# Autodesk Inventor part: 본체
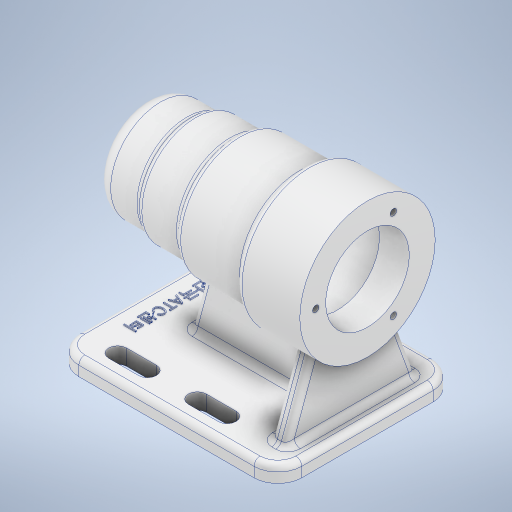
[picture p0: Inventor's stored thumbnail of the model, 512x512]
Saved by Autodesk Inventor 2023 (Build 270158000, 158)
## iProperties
Created: 2022-07
Part Number: 본체
Material: 알루미늄 6061
Document SubType Name: Modeling
Designer: owner
Density: 2.7 g/cm^3
Appearance: 알루미늄 - 평지
Author: owner
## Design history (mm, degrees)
sketch "스케치1"
  geometry: L1 (0, 0)-(112, 0); L2 (0, 0)-(0, 25); L3 (0, 25)-(24, 25); L4 (24, 25)-(24, 27); L5 (24, 27)-(46, 27); L6 (46, 27)-(46, 30); L7 (46, 30)-(80, 30); L8 (80, 30)-(80, 34); L9 (80, 34)-(112, 34); L10 (112, 34)-(112, 21); L11 (112, 21)-(97, 21); L12 (97, 21)-(97, 24); L13 (97, 24)-(43, 24); L14 (43, 24)-(43, 21); L15 (43, 21)-(31, 21); L16 (31, 21)-(31, 17.5); L17 (31, 17.5)-(13.3, 17.5); L18 (13, 17.2)-(13, 16); L19 (13, 16)-(9.3, 16); L20 (9, 15.7)-(9, 10.5); L21 (9, 10.5)-(9, 10.5); L22 (6, 7.5)-(6, 0); A1 r 3 centre (9, 7.5) between (9, 10.5) and (6, 7.5); A2 r 0.3 centre (9.3, 15.7) between (9.3, 16) and (9, 15.7); A3 r 0.3 centre (13.3, 17.2) between (13.3, 17.5) and (13, 17.2); 4 further points
  constraints: 44 end point, 19 perpendicular, 8 point on line, 6 point on circle, 6 tangent, 3 centre point, 1 equal radius, 1 horizontal, 1 parallel, 1 vertical
  dimensions: "d0" = 112 distance of L1.start L1.end; "d1" = 42 diameter of L11 L1; "d2" = 48 diameter of L13 L1; "d3" = 68 diameter of L9 L1; "d4" = 42 diameter of L15 L1; "d5" = 35 diameter of L17 L1; "d6" = 32 diameter of L19 L1; "d7" = 21 diameter of L21 L1; "d8" = 50 diameter of L3 L1; "d9" = 54 diameter of L5 L1; "d10" = 60 diameter of L7 L1; "d11" = 24 distance of L2.end L3.end; "d12" = 46 distance between parallel lines of L2 L6; "d13" = 80 distance between parallel lines of L2 L8; "d14" = 15 distance of L10.end L11.end; "d15" = 54 distance of L12.end L13.end; "d16" = 12 distance of L14.end L15.end; "d17" = 18 distance of L16.end point (13, 17.5); "d18" = 3 distance of L20.end point (6, 10.5); "d19" = 4 distance of L18.end point (9, 16); "d20" = 3 radius of A1; "d21" = 0.3 radius of A2
revolve "회전1" sketch "스케치1" stored, may be unused: angle "d22" = 90 deg
fillet "모깎기1" dims "d23" = 8
node "작업 평면1"
sketch "스케치2"
  geometry: L1 (0, -45)-(-112, -45); L2 (-112, -45)-(-112, 45); L3 (-112, 45)-(0, 45); L4 (0, 45)-(0, -45); L5 (0, 17)-(0, -17) reference; L6 (-112, 34)-(-112, -34) reference; 2 further points
  constraints: 8 end point, 2 parallel, 1 horizontal, 1 midpoint, 1 perpendicular
  dimensions: "d25" = 0 distance between parallel lines of L4 L5; "d26" = 0 distance between parallel lines of L6 L2; "d27" = 90 distance of L3.end L1.start; "d28" = 45 distance from line of point (0, 0) L1
extrude "돌출1" join sketch "스케치2" distance "d29" = 8; taper "d30" = 0 deg
fillet "모깎기2" dims "d31" = 12
fillet "모깎기3" dims "d32" = 3
sketch "스케치3"
  geometry: L1 (19.5, 33)-(34.5, 33); L2 (19.5, 28.5)-(34.5, 28.5); L3 (34.5, 37.5)-(19.5, 37.5); L4 (19.5, -33)-(34.5, -33); L5 (19.5, -37.5)-(34.5, -37.5); L6 (34.5, -28.5)-(19.5, -28.5); L7 (59.5, -33)-(74.5, -33); L8 (59.5, -37.5)-(74.5, -37.5); L9 (74.5, -28.5)-(59.5, -28.5); L10 (59.5, 33)-(74.5, 33); L11 (59.5, 28.5)-(74.5, 28.5); L12 (74.5, 37.5)-(59.5, 37.5); L13 (112, -33)-(112, 33) reference; A1 r 4.5 centre (19.5, 33) between (19.5, 37.5) and (19.5, 28.5); A2 r 4.5 centre (34.5, 33) between (34.5, 28.5) and (34.5, 37.5); A3 r 4.5 centre (19.5, -33) between (19.5, -28.5) and (19.5, -37.5); A4 r 4.5 centre (34.5, -33) between (34.5, -37.5) and (34.5, -28.5); A5 r 4.5 centre (59.5, -33) between (59.5, -28.5) and (59.5, -37.5); A6 r 4.5 centre (74.5, -33) between (74.5, -37.5) and (74.5, -28.5); A7 r 4.5 centre (59.5, 33) between (59.5, 37.5) and (59.5, 28.5); A8 r 4.5 centre (74.5, 33) between (74.5, 28.5) and (74.5, 37.5); 5 further points
  constraints: 32 end point, 16 point on circle, 16 tangent, 8 centre point, 5 parallel, 4 midpoint, 4 point on line, 1 horizontal
  dimensions: "d33" = 9 diameter of A2; "d34" = 9 diameter of A4; "d35" = 9 diameter of A6; "d36" = 9 diameter of A8; "d37" = 85 distance from line of L13 point (27, 33); "d38" = 85 distance from line of L13 point (27, -33); "d39" = 33 distance from line of point (0, 0) L1; "d40" = 33 distance from line of L4 point (0, 0); "d41" = 15 distance of L4.start L4.end; "d42" = 15 distance of L7.start L7.end; "d43" = 25 distance of L7.start L4.end; "d44" = 15 distance of L1.start L1.end; "d45" = 15 distance of L10.start L10.end; "d46" = 25 distance of L10.start L1.end
extrude "돌출2" cut sketch "스케치3" stored distance "d47" = 8; taper "d48" = 0 deg
sketch "스케치4"
  geometry: L1 (27, 4)-(104, 4); L2 (104, 4)-(104, -4); L3 (104, -4)-(27, -4); L4 (27, -4)-(27, 4); L5 (112, -33)-(112, 33) reference; 1 further point
  constraints: 8 end point, 2 parallel, 1 horizontal, 1 perpendicular
  dimensions: "d49" = 8 distance between parallel lines of L5 L2; "d50" = 8 distance between parallel lines of L3 L1; "d51" = 4 distance from line of point (0, 0) L3; "d52" = 77 distance of L1.start L1.end
extrude "돌출3" join sketch "스케치4" stored distance "d53" = 10; taper "d54" = 0 deg
feature "면 기울기1" dims angle "d55" = 15 deg
sketch "스케치5"
  geometry: L1 (96, 33)-(104, 33); L2 (104, 33)-(104, -33); L3 (104, -33)-(96, -33); L4 (96, -33)-(96, 33); L5 (112, -33)-(112, 33) reference; 1 further point
  constraints: 8 end point, 2 parallel, 1 horizontal, 1 perpendicular
  dimensions: "d56" = 8 distance of L1.start L1.end; "d57" = 8 distance between parallel lines of L5 L2; "d58" = 66 distance of L1.end L2.end; "d59" = 33 distance from line of point (0, 0) L1
extrude "돌출4" join sketch "스케치5" stored distance "d60" = 10; taper "d61" = 0 deg; dims "d0" = 112, "d1" = 42, "d2" = 48, "d3" = 68, "d4" = 42, "d5" = 35, "d6" = 32, "d7" = 21, "d8" = 50, "d9" = 54, "d10" = 60, "d11" = 24, "d12" = 46, "d13" = 80, "d14" = 15, "d15" = 54, "d16" = 12, "d17" = 18, "d18" = 3, "d19" = 4, "d20" = 3, "d21" = 0.3
feature "면 기울기2" dims angle "d62" = 20 deg
feature "면 기울기3" dims angle "d63" = 20 deg
fillet "모깎기4" dims "d64" = 3
fillet "모깎기5" dims "d65" = 3
fillet "모깎기7" dims "d67" = 3
sketch "스케치6"
  geometry: 2 further points
  constraints: 1 other
  dimensions: "d68" = 0 vertical distance of point (0, 0) point (12, 0); "d69" = 12 distance of point (0, 0) point (12, 0)
feature "엠보싱1" sketch "스케치6" dims "d0" = 112, "d1" = 42, "d2" = 48, "d3" = 68, "d4" = 42, "d5" = 35, "d6" = 32, "d7" = 21, "d8" = 50, "d9" = 54, "d10" = 60, "d11" = 24, "d12" = 46, "d13" = 80, "d14" = 15, "d15" = 54, "d16" = 12, "d17" = 18, "d18" = 3, "d19" = 4, "d20" = 3, "d21" = 0.3, "d70" = 0.5, "d71" = 0
sketch "스케치7"
  geometry: C1 r 10.5 at (0, 0) reference; C2 r 26 at (0, 0); 5 further points
  constraints: 1 centre point, 1 coincident, 1 horizontal alignment, 5 other
  dimensions: "d73" = 0 vertical distance of point (0, 0) point (-26, 0); "d76" = 360 deg dimension on point (0, 0) point (-26, 0) (derived); "d78" = 52 diameter of C2
hole "구멍1" sketch "스케치7" at (-26, 0), (13, -22.517), (13, 22.517) diameter "d79" = 3.242; stored, may be unused: countersink angle "d83" = 90 deg, drill point angle "d85" = 118 deg; dims "d80" = 8, "d81" = 4, "d82" = 2, "d84" = 11
node "솔리드1"
feature "A9D066F2-1C7D-4E18-AEED-F7BC21143FA4" dims "d79" = 3.242, "d80" = 8, "d81" = 4, "d82" = 2, "d83" = 90 deg, "d84" = 11, "d85" = 118 deg
